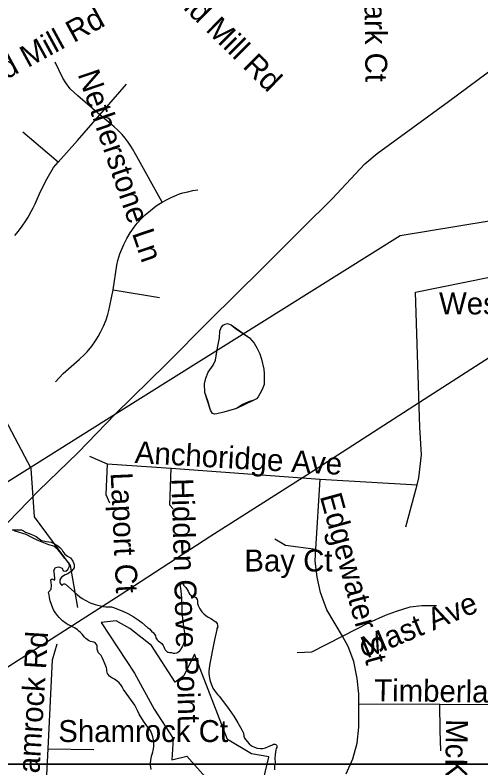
# Model space of a CAD drawing. Extents: x 1662474 to 1856135, y 779280 to 917889.
# Drawn here: x 1701086 to 1703100, y 826572 to 829831 of the extents above; entities that cross this region are included whole.
import ezdxf

# ---------------------------------------------------------------- set-up
doc = ezdxf.new("R2010")
doc.units = 0
for name, color, linetype in [('Exist Hydrographic Buffer Line', 7, 'Continuous'), ('Exist Hydrographic Lake Shore', 7, 'Continuous'), ('Exist Hydrographic Misc Water Feature', 7, 'Continuous'), ('Exist Road Non-System Type 51', 7, 'Continuous'), ('Exist Road Non-System Type 51 Label', 7, 'Continuous'), ('Exist Utilities Electrical Transmission Line', 7, 'Continuous'), ('Map Preparation Inset Cut Line', 7, 'Continuous')]:
    doc.layers.add(name, color=color, linetype=linetype)

msp = doc.modelspace()

# ---------------------------------------------------------------- linework, layer by layer
at = {"layer": 'Exist Hydrographic Buffer Line'}
for points in [[(1701861.1, 827065.1), (1701815.9, 826970.7), (1701777.6, 826943.2), (1701676.4, 827102.1), (1701582.6, 827175.8), (1701523.2, 827208.2), (1701458.5, 827201), (1701602, 826981.7), (1701687.5, 826826.3), (1701769.3, 826699.2), (1701763.1, 826607.3), (1701828, 826622.5), (1702002.2, 826427.9), (1702044.3, 826243.1), (1702070.3, 826171.7), (1702153.2, 826055.6), (1702169.2, 825911.6), (1702235.9, 825791.6), (1702327.1, 825685.3), (1702414.3, 825554.6), (1702287.7, 825455.1)], [(1702964.1, 826137.9), (1702860.1, 826096.3), (1702783.8, 826011.7), (1702637.3, 826000.4), (1702530.3, 826087.9), (1702435.7, 826198.2), (1702262.2, 826363.7), (1702159.6, 826522.1), (1702183.8, 826618.7), (1702183, 826620.3), (1702107.9, 826632.8), (1702004.2, 826695), (1701861.1, 827065.1)]]:
    msp.add_lwpolyline(points, dxfattribs=at)
at = {"layer": 'Exist Hydrographic Lake Shore'}
for points in [[(1701499.4, 826965.1), (1701494.1, 826969.6), (1701489.2, 826975.8), (1701486.2, 826980.8), (1701484.2, 826987.1), (1701483.1, 826992.6), (1701482.9, 826999.4), (1701481.4, 827004.9), (1701476.1, 827019.4), (1701467.6, 827037.5), (1701462.6, 827050.6), (1701458.2, 827058.8), (1701447.2, 827070.8), (1701443.2, 827077.7), (1701441.1, 827086.6), (1701441.1, 827096.3), (1701440.9, 827100), (1701439.1, 827104.9), (1701437, 827108.6), (1701433.9, 827111.8), (1701429.6, 827114.7), (1701426.2, 827116), (1701419.4, 827117.3), (1701412, 827119.9), (1701404.1, 827123.6), (1701397.6, 827127.8), (1701391.5, 827132.2), (1701386, 827137.5), (1701375.8, 827150.6), (1701368.5, 827158.5), (1701362.1, 827164.6), (1701355.6, 827170.1), (1701346.4, 827176.6), (1701337, 827182.1), (1701327.2, 827187.1), (1701315.5, 827191.6), (1701307.2, 827196.8), (1701291, 827208.9), (1701276.6, 827222.8), (1701269, 827231.8), (1701260.4, 827243.2), (1701254.2, 827253), (1701249, 827263.2), (1701237, 827296.1), (1701234.1, 827309.7), (1701232.8, 827320.9), (1701230.1, 827333.1), (1701241.8, 827345.6), (1701242.8, 827363.5), (1701240.6, 827386.9), (1701247, 827391.3), (1701256.4, 827384.5), (1701257.5, 827388.7), (1701256.4, 827411.5), (1701253.8, 827427), (1701260.6, 827439.1), (1701274.8, 827443), (1701289.5, 827437), (1701294.5, 827424.6), (1701305, 827424.4), (1701314.1, 827430.9), (1701320.8, 827446.2), (1701319.4, 827458.8), (1701300.8, 827479), (1701285.2, 827501), (1701271.1, 827518.1), (1701253.8, 827531.8), (1701231.5, 827538.3), (1701181.4, 827557.4), (1701158, 827570.1), (1701134.1, 827581.9), (1701086.9, 827596.3), (1701075, 827602.1), (1701101.5, 827602.1), (1701113.1, 827603.1), (1701122.2, 827598.9), (1701131.5, 827592.1), (1701151.1, 827586.1), (1701176.9, 827574.5), (1701190.2, 827563.8), (1701200, 827556.9), (1701222.2, 827551.9), (1701242, 827549.1), (1701256.4, 827541.9), (1701271.1, 827533.8), (1701280, 827526.8), (1701287.9, 827517.6), (1701291.9, 827508.6), (1701301, 827497.1), (1701312.9, 827488.9), (1701326, 827481.1), (1701336.1, 827466.6), (1701342, 827452.2), (1701342, 827438.6), (1701329.9, 827423.9), (1701314.1, 827412.6), (1701302.4, 827408.6), (1701286.6, 827398.1), (1701279, 827385.8), (1701279, 827373.8)], [(1701279, 827373.8), (1701287.9, 827362.2), (1701290.2, 827362.7), (1701292.1, 827365.9), (1701293.9, 827367.4), (1701296.2, 827368.5), (1701300, 827368.8), (1701303.6, 827367.7), (1701354, 827323.1), (1701366.1, 827313.4), (1701376.6, 827305.8), (1701407.2, 827288.9), (1701410.8, 827287.4), (1701432.8, 827279.2), (1701455.4, 827273.2), (1701466.9, 827271.4), (1701478.4, 827269.8), (1701490.2, 827269), (1701502.6, 827269), (1701512, 827266.1), (1701530.9, 827259.6), (1701555.4, 827249.6), (1701572.9, 827240.9), (1701596, 827227.8), (1701617.8, 827213.4), (1701633.8, 827201.3), (1701658.5, 827179.8), (1701666.9, 827174.2), (1701675.8, 827164.8), (1701684.8, 827156.7), (1701689.5, 827150.9), (1701693.4, 827144.3), (1701695.2, 827135.9), (1701697.4, 827130.9), (1701699.8, 827127.2), (1701705.2, 827122), (1701715.4, 827115.4), (1701720.6, 827110.8), (1701724.1, 827106.6), (1701727, 827101.8), (1701729.1, 827096.8), (1701731.5, 827089.2), (1701734.9, 827083.2), (1701737.5, 827080), (1701741.1, 827076.9), (1701745.6, 827074), (1701749.2, 827072.7), (1701755.4, 827071.4), (1701761.6, 827071.4), (1701770, 827069), (1701776.4, 827068.8), (1701785, 827070.3), (1701790, 827072.7), (1701796.8, 827077.9), (1701799.8, 827081.1), (1701806.5, 827091.6), (1701810.8, 827098.9), (1701815.8, 827111), (1701819.4, 827125.4), (1701821, 827137), (1701820.6, 827148.5), (1701819.9, 827156.9), (1701815.1, 827184.2), (1701811, 827217.1), (1701808.9, 827249.8), (1701806.5, 827307.6), (1701803.9, 827338.8), (1701801.5, 827358.5), (1701800.2, 827362.4), (1701800.8, 827365.3), (1701801.5, 827367.2), (1701803.9, 827369.2), (1701807.9, 827370.3), (1701811, 827369.5), (1701813.9, 827366.9), (1701814.9, 827362.9), (1701823.6, 827353.8), (1701830.6, 827344.3), (1701834.6, 827337.2), (1701835.9, 827332.8), (1701837.5, 827329.6), (1701841.6, 827323.6), (1701844.6, 827321.2), (1701848.5, 827318.9), (1701852.8, 827317.1), (1701856.6, 827316), (1701862.4, 827313.1), (1701867.1, 827309.2), (1701870.2, 827305.2), (1701872.6, 827300.8), (1701874.5, 827296.1), (1701875.2, 827289.8), (1701874.8, 827283.7), (1701877.9, 827275.1), (1701881.6, 827266.6), (1701885.2, 827260.3), (1701893.6, 827248.2), (1701902.2, 827238.8), (1701910.5, 827231.4), (1701921.2, 827224.1)], [(1701921.2, 827224.1), (1701932.5, 827218.4), (1701939.4, 827214.9), (1701946.6, 827209.2), (1701954, 827204.9), (1701959.2, 827197.1), (1701961.9, 827188.2), (1701962.4, 827182.9), (1701959, 827176.1), (1701958.2, 827171.1), (1701948.2, 827127), (1701939.4, 827083.4), (1701926.5, 827015.4), (1701924.6, 827002.3), (1701924.1, 826991.8), (1701924.4, 826981.1), (1701925.4, 826970.6), (1701927.2, 826960.1), (1701930.1, 826947.2), (1701936.1, 826928.6), (1701941.1, 826917.8), (1701955.6, 826897.1), (1701962.1, 826888.9), (1701968.2, 826882.7), (1701991.8, 826852.5), (1702012, 826824.6), (1702031.5, 826796.1), (1702049.5, 826766.9), (1702066.9, 826737), (1702073.8, 826722.8), (1702075, 826709.7), (1702078.4, 826701.3), (1702088.9, 826686.1), (1702098.1, 826676.4), (1702108.9, 826668.2), (1702120.6, 826662.2), (1702133.2, 826658.2), (1702146.6, 826656.7), (1702157.4, 826656.9), (1702169, 826659.1), (1702181.6, 826665.6), (1702199.1, 826672.7), (1702203.9, 826675.3), (1702206.2, 826675.6), (1702209.6, 826675.1), (1702213.1, 826673.8), (1702215.8, 826671.1), (1702217.2, 826668.2), (1702218, 826663.5), (1702217.2, 826660.1), (1702215.4, 826656.9), (1702213.6, 826650.9), (1702210.1, 826630.9), (1702209.1, 826613.4), (1702209.9, 826595.8), (1702208.4, 826584.5), (1702207.9, 826575.3), (1702208.1, 826564)], [(1701536.1, 826940.9), (1701528, 826948.2), (1701516.5, 826956.4), (1701504.1, 826962.2), (1701499.4, 826965.1)], [(1701673.8, 826565.9), (1701671.9, 826584.5), (1701671.9, 826594.2), (1701672.6, 826603.9), (1701676.1, 826622.8), (1701678.8, 826632), (1701682.1, 826641.2), (1701683.6, 826648.2), (1701685.2, 826663), (1701685.5, 826675.1), (1701684.5, 826692.1), (1701681.9, 826706.6), (1701677.4, 826720.4), (1701671.4, 826734.9), (1701655.9, 826754.6), (1701641.4, 826775.1), (1701623, 826804.9), (1701614.6, 826820.7), (1701603.4, 826843.3), (1701578.1, 826880.3), (1701554.8, 826912.1), (1701549.5, 826923.3), (1701543.2, 826932.5), (1701536.1, 826940.9)]]:
    msp.add_lwpolyline(points, dxfattribs=at)
at = {"layer": 'Exist Hydrographic Misc Water Feature'}
for points in [[(1701357, 827267.3), (1701326.1, 827448.5), (1701170, 827658.5), (1701155, 827868.8), (1700959, 828237.2), (1700169, 829178.9), (1700005, 829454.6), (1699824.4, 829654.8)], [(1702099.4, 828433.1), (1702119.7, 828411.3), (1702130.8, 828390.6), (1702144.5, 828364.9), (1702151.7, 828341), (1702161.4, 828298), (1702163.3, 828280), (1702163.1, 828255.4), (1702162.6, 828231.6), (1702154.3, 828209.6), (1702144.2, 828191.7), (1702136.4, 828177.9), (1702130, 828169.9), (1702117.7, 828163.6), (1702095.7, 828156.6), (1702069.6, 828144.8), (1702043.3, 828127.3), (1701989.1, 828112), (1701958.9, 828104.4), (1701947.8, 828103.8), (1701939.1, 828106.4), (1701931.2, 828120.6), (1701919.9, 828161), (1701906.3, 828197.4), (1701904.5, 828235.2), (1701910.7, 828259.7), (1701921.4, 828284.9), (1701942.5, 828315.6), (1701951.9, 828336.8), (1701956.4, 828366.3), (1701962.9, 828398.1), (1701969.3, 828434), (1701971.8, 828462.8), (1701976.4, 828478.2), (1701986, 828487.9), (1701994.2, 828493.5), (1702004.3, 828495.8), (1702020.8, 828490.4), (1702037.9, 828475.4), (1702099.4, 828433.1)], [(1702099.4, 828433.1), (1702119.7, 828411.3), (1702130.8, 828390.6), (1702144.5, 828364.9), (1702151.7, 828341), (1702161.4, 828298), (1702163.3, 828280), (1702163.1, 828255.4), (1702162.6, 828231.6), (1702154.3, 828209.6), (1702144.2, 828191.7), (1702136.4, 828177.9), (1702130, 828169.9), (1702117.7, 828163.6), (1702043.3, 828127.3), (1701989.1, 828112), (1701958.9, 828104.4), (1701947.8, 828103.8), (1701939.1, 828106.4), (1701931.2, 828120.6), (1701906.3, 828197.4), (1701904.5, 828235.2), (1701910.7, 828259.7), (1701921.4, 828284.9), (1701942.5, 828315.6), (1701951.9, 828336.8), (1701962.9, 828398.1), (1701969.3, 828434), (1701971.8, 828462.8), (1701976.4, 828478.2), (1701986, 828487.9), (1701994.2, 828493.5), (1702004.3, 828495.8), (1702020.8, 828490.4), (1702099.4, 828433.1)]]:
    msp.add_lwpolyline(points, dxfattribs=at)
at = {"layer": 'Exist Road Non-System Type 51'}
for p, q in [((1701452.4, 829399.7), (1701567.6, 829531.9)), ((1701272.9, 829194.2), (1701119.6, 829323.5)), ((1701510.4, 828642.2), (1701710.1, 828608.9)), ((1701407.2, 827922.2), (1701483.4, 827888.2)), ((1701483.4, 827888.2), (1701760.4, 827870.2)), ((1701760.4, 827870.2), (1702405.6, 827822.2)), ((1702386.9, 827518.6), (1702405.6, 827822.2)), ((1702405.6, 827822.2), (1702825.1, 827797.4)), ((1702775.8, 827616.2), (1702825.1, 827797.4)), ((1702573.1, 826849), (1702922.5, 826848.8)), ((1702922.5, 826848.8), (1703498.9, 826845.4)), ((1701229.4, 826655.4), (1701427, 826651.9))]:
    msp.add_line(p, q, dxfattribs=at)
for points in [[(1701452.4, 829399.7), (1701357.1, 829481.9), (1701323.6, 829512), (1701305.1, 829537.4), (1701293.1, 829558.2), (1701259, 829627.2)], [(1701272.9, 829194.2), (1701356.4, 829288.6), (1701452.4, 829399.7)], [(1701722.5, 829021.2), (1701611.8, 829218.6), (1701607.2, 829228.2), (1701593.9, 829252.4), (1701586.9, 829263.9), (1701575, 829281), (1701562.4, 829297.6), (1701549.2, 829313.4), (1701539.9, 829323.2), (1701530.1, 829333), (1701514.9, 829347.2), (1701504.1, 829355.9), (1701488.1, 829368.7), (1701452.4, 829399.7)], [(1701084.8, 828876.9), (1701100.5, 828895.8), (1701117.2, 828917.8), (1701132.8, 828940.4), (1701142.8, 828956.1), (1701156.1, 828980.5), (1701164.5, 828997), (1701172.1, 829013.9), (1701180.8, 829034.6), (1701191, 829056.6), (1701213.4, 829101.2), (1701224.6, 829122.8), (1701252.6, 829171), (1701272.9, 829194.2)], [(1701722.5, 829021.2), (1701744, 829033), (1701764, 829042.4), (1701784.1, 829051.4), (1701797.4, 829056.4), (1701811.5, 829061.1), (1701832.5, 829066.4), (1701854, 829071.6), (1701875.8, 829075)], [(1701510.4, 828642.2), (1701526.1, 828747.9), (1701530.9, 828769.2), (1701539.4, 828797.6), (1701546.9, 828818), (1701555.9, 828838), (1701569, 828863.7), (1701583.9, 828888.7), (1701600.8, 828912.5), (1701613.9, 828929.9), (1701633.5, 828951.1), (1701649, 828966.6), (1701671.1, 828985.5), (1701688.4, 828999.2), (1701699.9, 829007.8), (1701722.5, 829021.2)], [(1702825.1, 827797.4), (1702832.4, 827827.8), (1702844, 827927.8), (1702836.9, 828047.7), (1702818, 828631.4), (1703138, 828696.2), (1703223.5, 828707.2), (1703273.1, 828702.6), (1703316.1, 828691.2), (1703363.4, 828670.5), (1703562.4, 828564.2), (1703628.5, 828534.9), (1703669.8, 828528.9), (1703744.8, 828520.4)], [(1701260.9, 828243.4), (1701294.5, 828279.5), (1701362.5, 828340), (1701386.9, 828362.7), (1701397.8, 828373.6), (1701417.9, 828397.9), (1701433.9, 828421.4), (1701445.6, 828439.9), (1701454.9, 828458.4), (1701468.4, 828484.4), (1701479.2, 828511.2), (1701486.8, 828534.8), (1701491.9, 828552.4), (1701496, 828572.6), (1701510.4, 828642.2)], [(1701483.4, 827888.2), (1701478.1, 827755.9), (1701494.6, 827719.4)], [(1701769.8, 827693.4), (1701755.1, 827708.9), (1701760.4, 827870.2)], [(1702209.4, 827563.2), (1702255.4, 827536.9), (1702386.9, 827518.6)], [(1702501.5, 827142.5), (1702434.6, 827255.9), (1702406.8, 827330.9), (1702392.4, 827398.4), (1702383.9, 827469), (1702386.9, 827518.6)], [(1702501.5, 827142.5), (1702617.2, 827201.5), (1702687.4, 827233.6), (1702735.9, 827251.4), (1702794.4, 827269.2), (1702845.4, 827275.2), (1702908.4, 827275)], [(1702305.1, 827071.6), (1702368.6, 827074.5), (1702501.5, 827142.5)], [(1702573.1, 826849), (1702573.1, 826892.9), (1702565.9, 826959.9), (1702550.6, 827033.2), (1702525.6, 827097.1), (1702501.5, 827142.5)], [(1701229.4, 826655.4), (1701248, 827039.6), (1701268.1, 827109.7)], [(1702517.2, 826546.2), (1702546.1, 826611.8), (1702565.9, 826679.5), (1702571.9, 826748), (1702573.1, 826849)], [(1702926.9, 826646.8), (1702924.6, 826734.4), (1702922.5, 826848.8)], [(1701191.2, 826289.8), (1701204.9, 826327), (1701216.2, 826402.6), (1701229.4, 826655.4)]]:
    msp.add_lwpolyline(points, dxfattribs=at)
at = {"layer": 'Exist Utilities Electrical Transmission Line'}
for points in [[(1701520.4, 828105.5), (1701738.8, 828319.2), (1701924.9, 828507.3), (1702155.5, 828734.8), (1702327.5, 828907), (1702457, 829035.6), (1702598.5, 829186.2), (1702651.1, 829231.6), (1702959.6, 829456.3), (1703332.8, 829734.2), (1703510.4, 829864.3), (1703766.6, 830053.6), (1704004.4, 830225.1), (1704278.8, 830424.2), (1704376.8, 830502), (1704694.3, 830746.7), (1705090.4, 831084.8)], [(1698412.5, 825294.6), (1698803.4, 825554.4), (1700105.2, 826390.5), (1700818.4, 826854.9), (1701078.4, 827026.1), (1701539.9, 827321.1), (1701932.7, 827576.9), (1702347.7, 827840.4), (1702855.5, 828168.9), (1703464, 828560.4), (1704177.3, 829020.8), (1704330.5, 829125.1)], [(1701520.4, 828105.5), (1702751.3, 828876.4), (1703635.2, 829022.8), (1704186.3, 829106.6), (1704330.5, 829125.1)], [(1692929.2, 823686.1), (1695261.2, 824166.9), (1701520.4, 828105.5)], [(1698412.5, 825294.6), (1699147.3, 825882.8), (1699284.5, 825997.3), (1699599.4, 826250), (1700023.5, 826605.4), (1700136.8, 826718.2), (1700328.8, 826908.2), (1700598, 827177.3), (1700966.1, 827545.4), (1701186.6, 827771.1), (1701358.5, 827937.3), (1701520.4, 828105.5)]]:
    msp.add_lwpolyline(points, dxfattribs=at)
at = {"layer": 'Map Preparation Inset Cut Line'}
for points in [[(1731035.7, 826588.1), (1668486.3, 826588.1), (1668486.3, 870408.9), (1731035.7, 870408.9)], [(1731035.7, 782767.4), (1668486.3, 782767.4), (1668486.3, 826588.1), (1731035.7, 826588.1)]]:
    msp.add_lwpolyline(points, close=True, dxfattribs=at)

# ---------------------------------------------------------------- texts
at = {"layer": 'Exist Road Non-System Type 51 Label'}
for s, rotation, p in [('Ashley Park Ct', 270.6615, (1702591.3, 830380.9)), ('Old Mill Rd', 315.2505, (1701740.6, 829929.2)), ('Old Mill Rd', 28.5958, (1700936.2, 829489.8)), ('Netherstone Ln', 288.8424, (1701355.6, 829575.3)), ('Anchoridge Ave', 356.6963, (1701601.9, 827892.4)), ('Laport Ct', 272.6011, (1701499, 827849.3)), ('Hidden Cove Point', 271.6356, (1701761.6, 827824.9)), ('Edgewater St', 285.4138, (1702403.1, 827748)), ('Mast Ave', 22.8453, (1702607.2, 827045.3)), ('Shamrock Rd', 86.4257, (1701181.5, 826392.1)), ('Timberlane Dr', 359.2853, (1702638.4, 826861.3)), ('McKinley St', 269.0765, (1702950, 826784))]:
    msp.add_text(s, height=95, rotation=rotation, dxfattribs=at).set_placement(p)
for s, p in [('Wesseck Dr', (1702919.2, 828535.3)), ('Bay Ct', (1702077.5, 827422.4)), ('Shamrock Ct', (1701272.7, 826684.3))]:
    msp.add_text(s, height=95, dxfattribs=at).set_placement(p)

doc.saveas('drawing.dxf')
